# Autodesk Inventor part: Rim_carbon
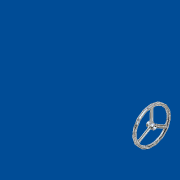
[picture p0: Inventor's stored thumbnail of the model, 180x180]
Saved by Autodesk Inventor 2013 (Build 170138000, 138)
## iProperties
Shininess: 64.0
Length Units: 11269
Angle Units: 11279
Time Units: 11290
Mass Units: 11283
Length Display Precision: 3
Angle Display Precision: 2
Compacted: True
Part Number: Rim_carbon
Document SubType Name: Modeling
Created: 2002-10
Designer: roithn
Density: 11.37 g/cm^3
Material: Generic
Density: 0.0
Volumn: 0.0
Area: 0.0
PropertySet Name: Model Information
Control State: 0
Master: False
Checked Out: False
Author: roithn
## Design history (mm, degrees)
node "Sketch1"
revolve "Revolution1" stored, may be unused: angle "d0" = 90 deg
fillet "Fillet1" dims "d1" = 10
feature "Rib1" dims "d2" = 1, "d3" = 6
sketch "Sketch3"
  geometry: L1 (1467.837, 205.54)-(1467.837, 357.873); L2 (1494.637, 192.54)-(1504.637, 192.54); L3 (1504.637, 192.54)-(1504.637, 195.54); L4 (1504.637, 195.54)-(1425.037, 195.54); L5 (1425.037, 195.54)-(1425.037, 192.54); L6 (1425.037, 192.54)-(1435.037, 192.54); L7 (1435.037, 192.54)-(1435.037, 189.54); L8 (1435.037, 189.54)-(1494.637, 189.54); L9 (1494.637, 189.54)-(1494.637, 192.54); L10 (1425.037, 200.54)-(1425.037, 195.54); L11 (1425.037, 195.54)-(1504.637, 195.54); L12 (1504.637, 195.54)-(1504.637, 200.54); L13 (1499.637, 205.54)-(1430.037, 205.54); L14 (38.427, -38.422)-(145.912, -103.005); L15 (18.926, 116.942)-(21.114, -8.435); L16 (1473.101, 367.306)-(1472.27, 366.382); L17 (1477.808, 205.54)-(1473.101, 367.306); L18 (1451.866, 205.54)-(1477.808, 205.54); L19 (1456.573, 367.306)-(1451.866, 205.54); L20 (1457.404, 366.382)-(1456.573, 367.306); L21 (1425.037, 176.54)-(1504.637, 176.54); L22 (9.5, -27.626)-(-3.5, -50.143); L23 (-8.258, -32.384)-(14.258, -45.384); L24 (1478.587, 389.04)-(1477.137, 389.04); L25 (1479.837, 377.169)-(1479.837, 387.79); L26 (1472.27, 366.382)-(1478.245, 373.022); L27 (1451.428, 373.022)-(1457.404, 366.382); L28 (1449.837, 387.79)-(1449.837, 377.169); L29 (1452.537, 389.04)-(1451.087, 389.04); L30 (1453.837, 387.04)-(1453.837, 387.74); L31 (1451.837, 381.29)-(1451.837, 385.04); L32 (1461.837, 205.54)-(1467.837, 205.54); L33 (1461.837, 357.873)-(1461.837, 205.54); L34 (1473.105, 375.29)-(1456.568, 375.29); L35 (1470.783, 367.72)-(1474.592, 371.952); L36 (1455.082, 371.952)-(1458.89, 367.72); L37 (1473.837, 377.29)-(1455.837, 377.29); L38 (1477.837, 385.04)-(1477.837, 381.29); L39 (1475.837, 387.74)-(1475.837, 387.04); C1 r 19 at (3, -38.884) reference; A1 r 10 centre (1477.837, 357.873) between (1471.337, 365.472) and (1467.837, 357.873); A2 r 5 centre (1499.637, 200.54) between (1504.637, 200.54) and (1499.637, 205.54); A3 r 5 centre (1430.037, 200.54) between (1430.037, 205.54) and (1425.037, 200.54); A4 r 25 centre (43.922, 117.378) between (50.256, 141.562) and (18.926, 116.942); A5 r 186.532 centre (3, -38.884) between (182.899, -88.183) and (50.256, 141.562); A6 r 25 centre (158.788, -81.576) between (145.912, -103.005) and (182.899, -88.183); A7 r 20 centre (48.728, -21.278) between (30.063, -28.464) and (38.427, -38.422); A8 r 29 centre (3, -38.884) between (30.063, -28.464) and (25.556, -20.657); A9 r 20 centre (41.111, -8.086) between (21.114, -8.435) and (25.556, -20.657); A10 r 10 centre (1464.837, 373.072) between (1457.404, 366.382) and (1472.27, 366.382); A11 r 1.3 centre (1477.137, 387.74) between (1477.137, 389.04) and (1475.837, 387.74); A12 r 1.25 centre (1478.587, 387.79) between (1479.837, 387.79) and (1478.587, 389.04); A13 r 6.2 centre (1473.637, 377.169) between (1478.245, 373.022) and (1479.837, 377.169); A14 r 10 centre (1464.837, 373.072) between (1457.404, 366.382) and (1472.27, 366.382); A15 r 6.2 centre (1456.037, 377.169) between (1449.837, 377.169) and (1451.428, 373.022); A16 r 1.25 centre (1451.087, 387.79) between (1451.087, 389.04) and (1449.837, 387.79); A17 r 1.3 centre (1452.537, 387.74) between (1453.837, 387.74) and (1452.537, 389.04); A18 r 1 centre (1452.837, 387.04) between (1452.837, 386.04) and (1453.837, 387.04); A19 r 1 centre (1452.837, 385.04) between (1452.837, 386.04) and (1451.837, 385.04); A20 r 10 centre (1451.837, 357.873) between (1461.837, 357.873) and (1458.337, 365.472); A21 r 10 centre (1464.837, 373.072) between (1458.337, 365.472) and (1471.337, 365.472); A22 r 2 centre (1456.568, 373.29) between (1456.568, 375.29) and (1455.082, 371.952); A23 r 2 centre (1473.105, 373.29) between (1474.592, 371.952) and (1473.105, 375.29); A24 r 8 centre (1464.837, 373.072) between (1458.89, 367.72) and (1470.783, 367.72); A25 r 4 centre (1455.837, 381.29) between (1451.837, 381.29) and (1455.837, 377.29); A26 r 4 centre (1473.837, 381.29) between (1473.837, 377.29) and (1477.837, 381.29); A27 r 1 centre (1476.837, 385.04) between (1477.837, 385.04) and (1476.837, 386.04); A28 r 1 centre (1476.837, 387.04) between (1475.837, 387.04) and (1476.837, 386.04)
  constraints: 78 end point, 60 point on circle, 28 centre point, 8 point on line, 4 midpoint, 1 concentric
extrude "Extrusion1" cut sketch "Sketch3" stored distance "d4" = 10; taper "d5" = 0 deg
fillet "Fillet2" dims "d6" = 10
fillet "Fillet3" dims "d7" = 1
pattern_circular "Circular Pattern1" dims "d10" = 360 deg
feature "Rib2" dims "d17" = 1, "d18" = 6
pattern_circular "Circular Pattern2" dims "d23" = 360 deg
body "Solid1"
sketch "Sketch2"
  geometry: L1 (1467.837, 205.54)-(1467.837, 357.873); L2 (1494.637, 192.54)-(1504.637, 192.54); L3 (1504.637, 192.54)-(1504.637, 195.54); L4 (1504.637, 195.54)-(1425.037, 195.54); L5 (1425.037, 195.54)-(1425.037, 192.54); L6 (1425.037, 192.54)-(1435.037, 192.54); L7 (1435.037, 192.54)-(1435.037, 189.54); L8 (1435.037, 189.54)-(1494.637, 189.54); L9 (1494.637, 189.54)-(1494.637, 192.54); L10 (1425.037, 200.54)-(1425.037, 195.54); L11 (1425.037, 195.54)-(1504.637, 195.54); L12 (1504.637, 195.54)-(1504.637, 200.54); L13 (1499.637, 205.54)-(1430.037, 205.54); L14 (1192.755, 177.003)-(1300.24, 112.419); L15 (1173.254, 332.366)-(1175.442, 206.989); L16 (1473.101, 367.306)-(1472.27, 366.382); L17 (1477.808, 205.54)-(1473.101, 367.306); L18 (1451.866, 205.54)-(1477.808, 205.54); L19 (1456.573, 367.306)-(1451.866, 205.54); L20 (1457.404, 366.382)-(1456.573, 367.306); L21 (1425.037, 176.54)-(1504.637, 176.54); L22 (1163.828, 187.798)-(1150.828, 165.282); L23 (1146.07, 183.04)-(1168.586, 170.04); L24 (1478.587, 389.04)-(1477.137, 389.04); L25 (1479.837, 377.169)-(1479.837, 387.79); L26 (1472.27, 366.382)-(1478.245, 373.022); L27 (1451.428, 373.022)-(1457.404, 366.382); L28 (1449.837, 387.79)-(1449.837, 377.169); L29 (1452.537, 389.04)-(1451.087, 389.04); L30 (1453.837, 387.04)-(1453.837, 387.74); L31 (1451.837, 381.29)-(1451.837, 385.04); L32 (1461.837, 205.54)-(1467.837, 205.54); L33 (1461.837, 357.873)-(1461.837, 205.54); L34 (1473.105, 375.29)-(1456.568, 375.29); L35 (1470.783, 367.72)-(1474.592, 371.952); L36 (1455.082, 371.952)-(1458.89, 367.72); L37 (1473.837, 377.29)-(1455.837, 377.29); L38 (1477.837, 385.04)-(1477.837, 381.29); L39 (1475.837, 387.74)-(1475.837, 387.04); A1 r 10 centre (1477.837, 357.873) between (1471.337, 365.472) and (1467.837, 357.873); A2 r 5 centre (1499.637, 200.54) between (1504.637, 200.54) and (1499.637, 205.54); A3 r 5 centre (1430.037, 200.54) between (1430.037, 205.54) and (1425.037, 200.54); A4 r 25 centre (1198.25, 332.802) between (1204.584, 356.987) and (1173.254, 332.366); A5 r 186.532 centre (1157.328, 176.54) between (1337.227, 127.241) and (1204.584, 356.987); A6 r 25 centre (1313.116, 133.848) between (1300.24, 112.419) and (1337.227, 127.241); A7 r 20 centre (1203.056, 194.146) between (1184.391, 186.96) and (1192.755, 177.003); A8 r 29 centre (1157.328, 176.54) between (1184.391, 186.96) and (1179.884, 194.767); A9 r 20 centre (1195.439, 207.338) between (1175.442, 206.989) and (1179.884, 194.767); A10 r 10 centre (1464.837, 373.072) between (1457.404, 366.382) and (1472.27, 366.382); A11 r 1.3 centre (1477.137, 387.74) between (1477.137, 389.04) and (1475.837, 387.74); A12 r 1.25 centre (1478.587, 387.79) between (1479.837, 387.79) and (1478.587, 389.04); A13 r 6.2 centre (1473.637, 377.169) between (1478.245, 373.022) and (1479.837, 377.169); A14 r 10 centre (1464.837, 373.072) between (1457.404, 366.382) and (1472.27, 366.382); A15 r 6.2 centre (1456.037, 377.169) between (1449.837, 377.169) and (1451.428, 373.022); A16 r 1.25 centre (1451.087, 387.79) between (1451.087, 389.04) and (1449.837, 387.79); A17 r 1.3 centre (1452.537, 387.74) between (1453.837, 387.74) and (1452.537, 389.04); A18 r 1 centre (1452.837, 387.04) between (1452.837, 386.04) and (1453.837, 387.04); A19 r 1 centre (1452.837, 385.04) between (1452.837, 386.04) and (1451.837, 385.04); A20 r 10 centre (1451.837, 357.873) between (1461.837, 357.873) and (1458.337, 365.472); A21 r 10 centre (1464.837, 373.072) between (1458.337, 365.472) and (1471.337, 365.472); A22 r 2 centre (1456.568, 373.29) between (1456.568, 375.29) and (1455.082, 371.952); A23 r 2 centre (1473.105, 373.29) between (1474.592, 371.952) and (1473.105, 375.29); A24 r 8 centre (1464.837, 373.072) between (1458.89, 367.72) and (1470.783, 367.72); A25 r 4 centre (1455.837, 381.29) between (1451.837, 381.29) and (1455.837, 377.29); A26 r 4 centre (1473.837, 381.29) between (1473.837, 377.29) and (1477.837, 381.29); A27 r 1 centre (1476.837, 385.04) between (1477.837, 385.04) and (1476.837, 386.04); A28 r 1 centre (1476.837, 387.04) between (1475.837, 387.04) and (1476.837, 386.04)
  constraints: 78 end point, 60 point on circle, 28 centre point, 8 point on line, 4 midpoint
fillet "Fillet4" dims "d19" = 10
fillet "Fillet5" dims "d20" = 1
fillet "Fillet6" dims "d24" = 0.5
fillet "Fillet7" dims "d25" = 0.5
